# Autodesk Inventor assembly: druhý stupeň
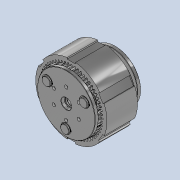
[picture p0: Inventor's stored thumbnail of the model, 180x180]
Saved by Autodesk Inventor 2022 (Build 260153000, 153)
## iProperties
Created: 2025-05
Part Number: druhý stupeň
Document SubType Name: Assembly
Designer: jbart
Author: jbart
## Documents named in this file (12)
- C:\Users\jbart\OneDrive\Dokumenty\Inventor\Převodovka navijáku\druhý stupeň.iam
- C:\Users\jbart\OneDrive\Dokumenty\Inventor\Převodovka navijáku\Unášeč A-2.ipt
- C:\Users\jbart\OneDrive\Dokumenty\Inventor\Převodovka navijáku\Hřídel III.iam
- C:\Users\jbart\OneDrive\Dokumenty\Inventor\Převodovka navijáku\Distanční kroužek II.ipt
- C:\Users\jbart\OneDrive\Dokumenty\Inventor\Převodovka navijáku\Satelit B.iam
- C:\Users\jbart\OneDrive\Dokumenty\Inventor\Převodovka navijáku\Hřídel V.ipt
- C:\Users\jbart\OneDrive\Dokumenty\Inventor\Content Center Files\R2022\cs-CZ\CSN 02 4630\CSN 02 4630 - 6010.ipt
- C:\Users\jbart\OneDrive\Dokumenty\Inventor\Převodovka navijáku\Distanční kroužek.ipt
- C:\Users\jbart\OneDrive\Dokumenty\Inventor\Content Center Files\R2022\cs-CZ\CSN 02 2930\CSN 02 2930 - 50.ipt
- C:\Users\jbart\OneDrive\Dokumenty\Inventor\Převodovka navijáku\Unášeč B-1.ipt
- C:\Users\jbart\OneDrive\Dokumenty\Inventor\Převodovka navijáku\Unášeč B-2.ipt
- C:\Users\jbart\OneDrive\Dokumenty\Inventor\Převodovka navijáku\Korunové kolo 2.iam
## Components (30 placed, 11 different names)
1. Unášeč A-2:1 — Proti sobě:1, Stejný směr:1, Proti sobě:2, Proti sobě:4, Stejný směr:2, Proti sobě:45, Stejný směr:3, Proti sobě:46
2. Hřídel III:1 [sub-assembly] — Proti sobě:4, Stejný směr:2, Proti sobě:5, Stejný směr:4, Stejný směr:5, Stejný směr:6, Proti sobě:53
3. Distanční kroužek II:1 — Proti sobě:5
4. Satelit B:1 [sub-assembly] — Stejný směr:4, Stejný směr:7
5. Hřídel V:1 — Proti sobě:47
6. CSN 02 4630 6010:1
7. CSN 02 4630 6010:2
8. Distanční kroužek:1 — Proti sobě:55
9. Distanční kroužek:2
10. CSN 02 2930 50:1
11. CSN 02 2930 50:2 — Proti sobě:48
12. Satelit B:2 [sub-assembly] — Stejný směr:5
13. Hřídel V:2 — Proti sobě:49
14. CSN 02 4630 6010:3
15. CSN 02 4630 6010:4
16. Distanční kroužek:3
17. Distanční kroužek:4
18. CSN 02 2930 50:3
19. CSN 02 2930 50:4 — Proti sobě:50
20. Satelit B:3 [sub-assembly] — Stejný směr:6
21. Hřídel V:3 — Proti sobě:51, Proti sobě:54
22. CSN 02 4630 6010:5
23. CSN 02 4630 6010:6
24. Distanční kroužek:5
25. Distanční kroužek:6
26. CSN 02 2930 50:5
27. CSN 02 2930 50:6 — Proti sobě:52
28. Unášeč B-1:1 — Proti sobě:45, Stejný směr:3, Proti sobě:46, Proti sobě:47, Proti sobě:48, Proti sobě:49, Proti sobě:50, Proti sobě:51, Proti sobě:52
29. Unášeč B-2:1 — Proti sobě:53, Proti sobě:54, Proti sobě:55, Proti sobě:56
30. Korunové kolo 2:1 [sub-assembly] — Proti sobě:56, Stejný směr:7, Proti sobě:57, Stejný směr:8
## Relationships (25: Mate 17, Flush 8)
- Proti sobě:1 [Mate]: Unášeč A-2:1
- Stejný směr:1 [Flush]: Unášeč A-2:1
- Proti sobě:2 [Mate]: Unášeč A-2:1
- Proti sobě:4 [Mate]: Unášeč A-2:1 ↔ Hřídel III:1
- Stejný směr:2 [Flush]: Unášeč A-2:1 ↔ Hřídel III:1
- Proti sobě:5 [Mate]: Hřídel III:1 ↔ Distanční kroužek II:1
- Proti sobě:45 [Mate]: Unášeč A-2:1 ↔ Unášeč B-1:1
- Stejný směr:3 [Flush]: Unášeč A-2:1 ↔ Unášeč B-1:1
- Proti sobě:46 [Mate]: Unášeč A-2:1 ↔ Unášeč B-1:1
- Proti sobě:47 [Mate]: Hřídel V:1 ↔ Unášeč B-1:1
- Proti sobě:48 [Mate]: CSN 02 2930 50:2 ↔ Unášeč B-1:1
- Stejný směr:4 [Flush]: Hřídel III:1 ↔ Satelit B:1
- Proti sobě:49 [Mate]: Hřídel V:2 ↔ Unášeč B-1:1
- Proti sobě:50 [Mate]: CSN 02 2930 50:4 ↔ Unášeč B-1:1
- Stejný směr:5 [Flush]: Hřídel III:1 ↔ Satelit B:2
- Proti sobě:51 [Mate]: Hřídel V:3 ↔ Unášeč B-1:1
- Proti sobě:52 [Mate]: CSN 02 2930 50:6 ↔ Unášeč B-1:1
- Stejný směr:6 [Flush]: Hřídel III:1 ↔ Satelit B:3
- Proti sobě:53 [Mate]: Hřídel III:1 ↔ Unášeč B-2:1
- Proti sobě:54 [Mate]: Hřídel V:3 ↔ Unášeč B-2:1
- Proti sobě:55 [Mate]: Distanční kroužek:1 ↔ Unášeč B-2:1
- Proti sobě:56 [Mate]: Unášeč B-2:1 ↔ Korunové kolo 2:1
- Stejný směr:7 [Flush]: Satelit B:1 ↔ Korunové kolo 2:1
- Proti sobě:57 [Mate]: Korunové kolo 2:1
- Stejný směr:8 [Flush]: Korunové kolo 2:1
## Named parameters: d66_d56 = 0, d67_d57 = 0, d68_d58 = 0, d69_d46 = 0, d70_d47 = 0, d71_d48 = 0, d72_d49 = 0, d73_d50 = 0, d74_d51 = 0, d75_d52 = 0, d76_d53 = 0, d77_d54 = 0, d78_d55 = 0, d22_d66_d56 = 0, d23_d67_d57 = 0, d24_d68_d58 = 0, d25_d69_d46 = 0, d26_d70_d47 = 0, d27_d71_d48 = 0, d28_d72_d49 = 0, d29_d73_d50 = 0, d30_d74_d51 = 0, d31_d75_d52 = 0, d32_d76_d53 = 0, d33_d77_d54 = 0, d34_d78_d55 = 0, d35_d66_d56 = 0, d36_d67_d57 = 0, d37_d68_d58 = 0, d38_d69_d46 = 0, d39_d70_d47 = 0, d40_d71_d48 = 0, d41_d72_d49 = 0, d42_d73_d50 = 0, d43_d74_d51 = 0, d44_d75_d52 = 0, d45_d76_d53 = 0, d46_d77_d54 = 0, d47_d78_d55 = 0
